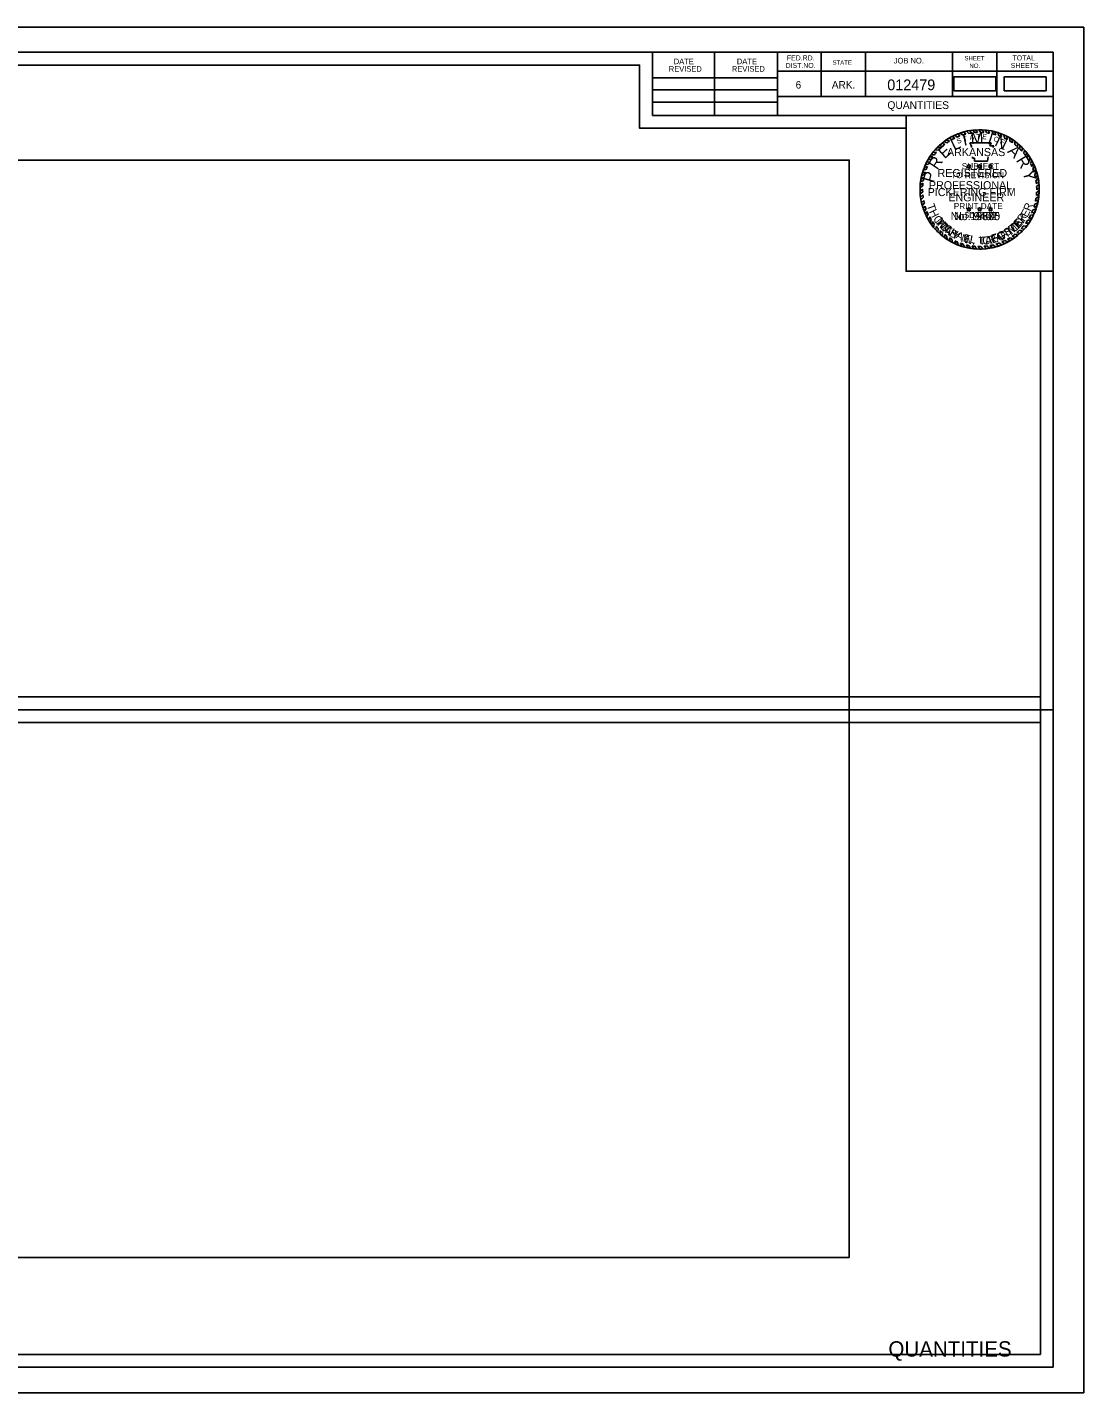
# Model space of a CAD drawing. Extents: x 1369290 to 1371547, y 379683 to 379897.
# Drawn here: x 1369823.5 to 1369988.6, y 379683.5 to 379896.8 of the extents above; entities that cross this region are included whole.
import ezdxf

# ---------------------------------------------------------------- set-up
doc = ezdxf.new("R2010")
doc.units = 0
for name, color, linetype in [('Default', 7, 'Continuous'), ('R_Border', 7, 'Continuous'), ('R_Border Notes', 7, 'Continuous'), ('R_Border Plan-Plan', 7, 'Continuous'), ('R_Border Title', 7, 'Continuous'), ('R_No Plot', 7, 'Continuous'), ('STAMP_PE_CRAFTON', 7, 'Continuous'), ('STAMP_PE_FOSTER', 7, 'Continuous'), ('STAMP_PE_SEAL-INFO', 7, 'Continuous'), ('STAMP_PE_TAEGTMEYER', 7, 'Continuous'), ('STAMP_PE_TXT', 7, 'Continuous'), ('STAMP_PRELIMINARY', 7, 'Continuous')]:
    doc.layers.add(name, color=color, linetype=linetype)

msp = doc.modelspace()

# ---------------------------------------------------------------- linework, layer by layer
at = {"layer": 'Default'}
for points in [[(1369968.28, 379886.89), (1369974.85, 379886.89), (1369974.85, 379889.08), (1369968.28, 379889.08)], [(1369976.15, 379886.89), (1369982.72, 379886.89), (1369982.72, 379889.08), (1369976.15, 379889.08)], [(1369691.88, 379704.61), (1369951.95, 379704.61), (1369951.95, 379876.08), (1369691.88, 379876.08)]]:
    msp.add_lwpolyline(points, close=True, dxfattribs=at)
at = {"layer": 'R_Border'}
for p, q in [((1369667.65, 379892.93), (1369983.83, 379892.93)), ((1369921.19, 379883.05), (1369921.19, 379892.93)), ((1369930.87, 379883.05), (1369930.87, 379892.93)), ((1369940.73, 379892.93), (1369940.73, 379883.05)), ((1369947.57, 379892.93), (1369947.57, 379885.99)), ((1369954.51, 379892.93), (1369954.51, 379885.99)), ((1369968.09, 379892.93), (1369968.09, 379885.99)), ((1369975.03, 379892.93), (1369975.03, 379885.99)), ((1369983.83, 379687.47), (1369983.83, 379892.93)), ((1369921.19, 379888.91), (1369940.73, 379888.91)), ((1369983.83, 379889.99), (1369940.73, 379889.99)), ((1369983.83, 379890.01), (1369983.83, 379890.01)), ((1369921.19, 379887.05), (1369940.73, 379887.05)), ((1369921.19, 379885.11), (1369940.73, 379885.11)), ((1369983.83, 379885.99), (1369940.73, 379885.99)), ((1369943.69, 379885.99), (1369983.83, 379885.99)), ((1369983.83, 379883.05), (1369921.19, 379883.05)), ((1369983.83, 379687.47), (1369667.65, 379687.47))]:
    msp.add_line(p, q, dxfattribs=at)
at = {"layer": 'R_Border Plan-Plan'}
msp.add_line((1369667.65, 379790.2), (1369983.83, 379790.2), dxfattribs=at)
at = {"layer": 'R_No Plot'}
for points in [[(1369655.25, 379896.82), (1369988.59, 379896.82), (1369988.59, 379683.48), (1369655.25, 379683.48)], [(1369981.83, 379792.2), (1369669.65, 379792.2), (1369669.65, 379890.93), (1369919.19, 379890.93), (1369919.19, 379881.05), (1369936.73, 379881.05), (1369960.83, 379881.05), (1369960.83, 379858.71), (1369981.83, 379858.71)], [(1369669.65, 379890.93), (1369919.19, 379890.93), (1369919.19, 379881.05), (1369936.73, 379881.05), (1369960.83, 379881.05), (1369960.83, 379858.71), (1369981.83, 379858.71), (1369981.83, 379689.47), (1369669.65, 379689.47)], [(1369960.83, 379883.05), (1369983.83, 379883.05), (1369983.83, 379858.71), (1369960.83, 379858.71)], [(1369669.65, 379788.2), (1369981.83, 379788.2), (1369981.83, 379689.47), (1369669.65, 379689.47)]]:
    msp.add_lwpolyline(points, close=True, dxfattribs=at)
at = {"layer": 'STAMP_PE_SEAL-INFO'}
for p, q in [((1369968.01, 379879.75), (1369968.47, 379879.52)), ((1369968.44, 379879.96), (1369968.83, 379879.68)), ((1369968.95, 379880.18), (1369969.24, 379879.85)), ((1369969.29, 379880.3), (1369969.67, 379880)), ((1369969.88, 379880.49), (1369970.17, 379880.14)), ((1369970.27, 379880.58), (1369970.63, 379880.24)), ((1369970.75, 379880.68), (1369971.05, 379880.31)), ((1369971.27, 379880.75), (1369971.55, 379880.37)), ((1369972.01, 379880.4), (1369971.69, 379880.79)), ((1369972.5, 379880.4), (1369972.22, 379880.81)), ((1369972.96, 379880.38), (1369972.7, 379880.81)), ((1369973.47, 379880.33), (1369973.18, 379880.77)), ((1369973.89, 379880.27), (1369973.64, 379880.72)), ((1369974.46, 379880.15), (1369974.28, 379880.61)), ((1369974.86, 379880.04), (1369974.7, 379880.51)), ((1369975.31, 379879.89), (1369975.17, 379880.37)), ((1369975.73, 379879.73), (1369975.58, 379880.23)), ((1369976.19, 379879.53), (1369976.09, 379880.02)), ((1369976.63, 379879.3), (1369976.55, 379879.81)), ((1369965.37, 379877.69), (1369965.89, 379877.65)), ((1369965.7, 379878.04), (1369966.24, 379877.99)), ((1369966.03, 379878.36), (1369966.49, 379878.22)), ((1369966.37, 379878.66), (1369966.9, 379878.56)), ((1369966.75, 379878.99), (1369967.21, 379878.78)), ((1369967.17, 379879.25), (1369967.61, 379879.05)), ((1369967.56, 379879.5), (1369967.99, 379879.27)), ((1369970.81, 379878.78), (1369974.15, 379878.78)), ((1369970.93, 379878.47), (1369970.81, 379878.78)), ((1369971.03, 379878.18), (1369970.93, 379878.47)), ((1369971.04, 379878.06), (1369971.03, 379878.18)), ((1369974.15, 379878.78), (1369973.93, 379878.29)), ((1369973.93, 379878.29), (1369974.56, 379878.29)), ((1369974.56, 379878.29), (1369974.41, 379878.06)), ((1369977.02, 379879.07), (1369976.98, 379879.57)), ((1369977.46, 379878.78), (1369977.42, 379879.3)), ((1369977.82, 379878.52), (1369977.85, 379879)), ((1369978.26, 379878.15), (1369978.28, 379878.67)), ((1369978.58, 379877.85), (1369978.65, 379878.35)), ((1369978.93, 379877.48), (1369979, 379878.01)), ((1369979.21, 379877.16), (1369979.35, 379877.63)), ((1369963.85, 379875.35), (1369964.35, 379875.46)), ((1369964.04, 379875.74), (1369964.54, 379875.81)), ((1369964.27, 379876.17), (1369964.76, 379876.19)), ((1369964.51, 379876.57), (1369965.03, 379876.6)), ((1369964.75, 379876.91), (1369965.25, 379876.91)), ((1369965.03, 379877.28), (1369965.58, 379877.3)), ((1369971.23, 379876.35), (1369971.2, 379876.57)), ((1369971.54, 379876.35), (1369971.23, 379876.35)), ((1369971.54, 379875.92), (1369971.54, 379876.35)), ((1369973.57, 379875.92), (1369971.54, 379875.92)), ((1369973.59, 379876.26), (1369973.57, 379875.92)), ((1369973.67, 379876.57), (1369973.59, 379876.26)), ((1369979.53, 379876.75), (1369979.67, 379877.25)), ((1369979.75, 379876.43), (1369979.93, 379876.89)), ((1369980.06, 379875.93), (1369980.24, 379876.42)), ((1369980.26, 379875.57), (1369980.49, 379876.01)), ((1369980.49, 379875.08), (1369980.72, 379875.57)), ((1369963.62, 379873.36), (1369963.15, 379873.11)), ((1369963.25, 379873.6), (1369963.72, 379873.8)), ((1369963.36, 379874.01), (1369963.84, 379874.18)), ((1369963.52, 379874.51), (1369964, 379874.65)), ((1369963.67, 379874.92), (1369964.17, 379875.07)), ((1369980.63, 379874.75), (1369980.9, 379875.18)), ((1369980.83, 379874.2), (1369981.1, 379874.67)), ((1369980.93, 379873.83), (1369981.23, 379874.28)), ((1369981.07, 379873.27), (1369981.39, 379873.72)), ((1369981.14, 379872.89), (1369981.49, 379873.25)), ((1369963.44, 379872.04), (1369963.02, 379871.78)), ((1369963.42, 379871.55), (1369963.02, 379871.21)), ((1369963.47, 379872.46), (1369963.04, 379872.18)), ((1369963.43, 379871.14), (1369963.04, 379870.81)), ((1369963.53, 379872.9), (1369963.09, 379872.68)), ((1369981.2, 379872.38), (1369981.57, 379872.72)), ((1369981.23, 379871.97), (1369981.62, 379872.26)), ((1369981.24, 379871.04), (1369981.66, 379871.32)), ((1369981.25, 379871.45), (1369981.65, 379871.77)), ((1369963.46, 379870.64), (1369963.09, 379870.29)), ((1369963.51, 379870.21), (1369963.16, 379869.84)), ((1369963.59, 379869.75), (1369963.25, 379869.39)), ((1369963.68, 379869.34), (1369963.37, 379868.92)), ((1369980.95, 379869.2), (1369981.42, 379869.4)), ((1369981.06, 379869.65), (1369981.51, 379869.84)), ((1369981.15, 379870.15), (1369981.59, 379870.37)), ((1369981.2, 379870.54), (1369981.63, 379870.79)), ((1369963.81, 379868.89), (1369963.51, 379868.47)), ((1369963.95, 379868.47), (1369963.67, 379868.05)), ((1369964.12, 379868.04), (1369963.85, 379867.62)), ((1369964.29, 379867.66), (1369964.06, 379867.19)), ((1369964.52, 379867.2), (1369964.33, 379866.71)), ((1369980.02, 379866.97), (1369980.52, 379867.03)), ((1369980.29, 379867.47), (1369980.78, 379867.54)), ((1369980.45, 379867.81), (1369980.94, 379867.9)), ((1369980.67, 379868.32), (1369981.15, 379868.45)), ((1369980.8, 379868.7), (1369981.29, 379868.9)), ((1369964.76, 379866.79), (1369964.57, 379866.32)), ((1369964.96, 379866.48), (1369964.85, 379865.93)), ((1369965.24, 379866.09), (1369965.14, 379865.56)), ((1369965.54, 379865.71), (1369965.46, 379865.19)), ((1369965.85, 379865.38), (1369965.79, 379864.85)), ((1369966.17, 379865.05), (1369966.14, 379864.52)), ((1369966.51, 379864.74), (1369966.51, 379864.21)), ((1369978.16, 379864.74), (1369978.63, 379864.61)), ((1369978.56, 379865.11), (1369979, 379864.97)), ((1369978.82, 379865.37), (1369979.29, 379865.29)), ((1369979.2, 379865.8), (1369979.66, 379865.73)), ((1369979.51, 379866.2), (1369980.01, 379866.2)), ((1369979.85, 379866.69), (1369980.32, 379866.69)), ((1369966.87, 379864.44), (1369966.89, 379863.92)), ((1369967.21, 379864.19), (1369967.25, 379863.68)), ((1369967.64, 379863.91), (1369967.7, 379863.4)), ((1369967.99, 379863.71), (1369968.08, 379863.19)), ((1369968.47, 379863.46), (1369968.63, 379862.94)), ((1369968.84, 379863.29), (1369969.02, 379862.78)), ((1369969.34, 379863.1), (1369969.55, 379862.59)), ((1369969.75, 379862.96), (1369969.97, 379862.47)), ((1369970.25, 379862.82), (1369970.47, 379862.36)), ((1369970.65, 379862.74), (1369970.9, 379862.28)), ((1369971.15, 379862.66), (1369971.39, 379862.21)), ((1369971.59, 379862.61), (1369971.86, 379862.18)), ((1369972.07, 379862.58), (1369972.38, 379862.17)), ((1369972.53, 379862.58), (1369972.88, 379862.18)), ((1369973.05, 379862.61), (1369973.38, 379862.23)), ((1369973.49, 379862.65), (1369973.86, 379862.29)), ((1369973.93, 379862.72), (1369974.32, 379862.38)), ((1369974.43, 379862.83), (1369974.8, 379862.5)), ((1369974.89, 379862.95), (1369975.3, 379862.65)), ((1369975.38, 379863.11), (1369975.82, 379862.84)), ((1369975.8, 379863.28), (1369976.22, 379863.02)), ((1369976.26, 379863.49), (1369976.74, 379863.28)), ((1369976.67, 379863.7), (1369977.08, 379863.47)), ((1369977.08, 379863.95), (1369977.53, 379863.75)), ((1369977.42, 379864.17), (1369977.86, 379863.98)), ((1369977.88, 379864.52), (1369978.35, 379864.37))]:
    msp.add_line(p, q, dxfattribs=at)
for radius, start, end in [(9.32, 117.6544, 120.8099), (9.32, 111.3124, 114.7026), (8.91, 110.3086, 113.1659), (9.32, 105.2339, 109.0352), (8.91, 104.0352, 107.3615), (9.32, 99.7525, 102.7765), (8.91, 98.258, 101.0329), (9.32, 93.9381, 96.5517), (8.91, 92.1102, 95.0367), (9.32, 87.7298, 90.6707), (8.91, 85.9628, 88.9097), (9.32, 81.9732, 84.8236), (8.91, 79.9264, 82.696), (9.32, 75.3125, 77.9426), (8.91, 73.5575, 76.2314), (9.32, 69.6061, 72.3058), (8.91, 67.6248, 70.504), (9.32, 63.1329, 66.2704), (9.32, 135.4021, 138.3031), (8.91, 133.1331, 136.2562), (9.32, 129.7326, 132.5376), (8.91, 127.5297, 130.9683), (9.32, 123.6199, 126.5906), (8.91, 121.9746, 125.11), (8.91, 115.6869, 119.1583), (8.91, 61.1558, 64.3784), (9.32, 56.9003, 60.0942), (8.91, 54.9238, 58.2702), (8.91, 48.3016, 52.0395), (9.32, 50.3492, 53.7159), (8.91, 42.2212, 45.5512), (9.32, 44.3405, 47.3929), (9.32, 38.1247, 41.2316), (9.32, 152.864, 155.5189), (9.32, 147.0072, 149.899), (8.91, 151.0315, 153.573), (9.32, 141.6056, 144.4486), (8.91, 145.0197, 148.2104), (8.91, 139.301, 142.5873), (8.91, 36.135, 39.5311), (8.91, 29.9032, 33.6645), (9.32, 31.9614, 35.4294), (8.91, 23.7732, 27.2211), (9.32, 25.9391, 29.0125), (9.32, 164.3068, 166.894), (9.32, 158.4077, 161.0701), (8.91, 167.9048, 170.9039), (8.91, 162.4331, 165.0013), (8.91, 156.3402, 159.2319), (8.91, 17.6802, 21.4251), (9.32, 19.9538, 23.3141), (8.91, 11.5444, 15.2364), (9.32, 13.8421, 17.4447), (9.32, 7.5852, 10.8621), (9.32, 175.7409, 178.2066), (9.32, 181.7251, 184.1626), (9.32, 170.0003, 172.6878), (8.91, 179.6454, 182.2633), (8.91, 173.73, 176.4734), (8.91, 5.7599, 9.0606), (8.91, 359.7329, 3.0639), (9.32, 1.7215, 4.7268), (9.32, 355.7156, 358.9569), (9.32, 187.4204, 190.1927), (9.32, 193.0369, 195.9973), (8.91, 185.4539, 188.234), (8.91, 191.2274, 193.9858), (8.91, 341.777, 345.0925), (8.91, 348.0778, 351.3435), (8.91, 353.8632, 357.1274), (9.32, 343.8925, 347.035), (9.32, 349.8305, 353.0885), (9.32, 198.8967, 201.6281), (8.91, 196.9675, 199.8353), (9.32, 204.5479, 207.4328), (8.91, 202.7761, 205.4791), (8.91, 208.7883, 211.7934), (8.91, 329.5549, 333.2076), (8.91, 335.6038, 339.1858), (9.32, 331.4037, 334.9332), (9.32, 337.3837, 340.9933), (9.32, 210.8636, 213.6571), (9.32, 216.6115, 219.491), (8.91, 214.1838, 217.2747), (9.32, 222.48, 225.3801), (8.91, 220.3909, 223.3056), (8.91, 226.2494, 229.2407), (8.91, 310.7744, 314.3161), (9.32, 312.4518, 315.6633), (8.91, 316.6531, 320.3711), (9.32, 318.2846, 321.8043), (8.91, 323.5851, 327.4407), (9.32, 325.4405, 328.9872), (9.32, 228.3665, 231.348), (8.91, 232.229, 234.9336), (9.32, 234.295, 236.9452), (8.91, 238.2223, 240.8353), (9.32, 240.1977, 242.8613), (8.91, 244.3204, 246.9486), (9.32, 246.576, 249.1558), (8.91, 250.3491, 253.1216), (9.32, 252.5967, 255.3252), (8.91, 256.505, 259.1192), (8.91, 262.3783, 265.2012), (8.91, 268.3215, 271.277), (8.91, 274.6157, 277.4486), (8.91, 280.3459, 283.5814), (8.91, 286.6423, 289.9783), (9.32, 288.5709, 291.9733), (8.91, 292.8745, 296.1185), (9.32, 294.6481, 298.2166), (8.91, 299.0768, 302.1724), (9.32, 300.621, 303.8703), (8.91, 304.823, 308.5143), (9.32, 306.3721, 310.208), (9.32, 258.4433, 261.1398), (9.32, 264.1978, 267.1009), (9.32, 270.2548, 273.3361), (9.32, 276.4239, 279.4357), (9.32, 282.3199, 285.3702)]:
    msp.add_arc((1369972.33, 379871.49), radius, start, end, dxfattribs=at)
at = {"layer": 'STAMP_PE_TXT'}
for p, q in [((1369970.56, 379875.21), (1369970.64, 379875.44)), ((1369970.64, 379875.44), (1369970.71, 379875.21)), ((1369972.26, 379875.21), (1369972.33, 379875.44)), ((1369972.33, 379875.44), (1369972.41, 379875.21)), ((1369973.96, 379875.21), (1369974.03, 379875.44)), ((1369974.03, 379875.44), (1369974.11, 379875.21)), ((1369970.51, 379875.06), (1369970.31, 379875.21)), ((1369970.31, 379875.21), (1369970.56, 379875.21)), ((1369970.44, 379874.83), (1369970.51, 379875.06)), ((1369970.64, 379874.97), (1369970.44, 379874.83)), ((1369970.83, 379874.83), (1369970.64, 379874.97)), ((1369970.71, 379875.21), (1369970.96, 379875.21)), ((1369970.96, 379875.21), (1369970.76, 379875.06)), ((1369970.76, 379875.06), (1369970.83, 379874.83)), ((1369972.21, 379875.06), (1369972.01, 379875.21)), ((1369972.01, 379875.21), (1369972.26, 379875.21)), ((1369972.14, 379874.83), (1369972.21, 379875.06)), ((1369972.33, 379874.97), (1369972.14, 379874.83)), ((1369972.53, 379874.83), (1369972.33, 379874.97)), ((1369972.41, 379875.21), (1369972.65, 379875.21)), ((1369972.65, 379875.21), (1369972.46, 379875.06)), ((1369972.46, 379875.06), (1369972.53, 379874.83)), ((1369973.91, 379875.06), (1369973.71, 379875.21)), ((1369973.71, 379875.21), (1369973.96, 379875.21)), ((1369973.83, 379874.83), (1369973.91, 379875.06)), ((1369974.03, 379874.97), (1369973.83, 379874.83)), ((1369974.23, 379874.83), (1369974.03, 379874.97)), ((1369974.11, 379875.21), (1369974.35, 379875.21)), ((1369974.35, 379875.21), (1369974.15, 379875.06)), ((1369974.15, 379875.06), (1369974.23, 379874.83)), ((1369970.51, 379868.35), (1369970.31, 379868.5)), ((1369970.31, 379868.5), (1369970.56, 379868.5)), ((1369970.44, 379868.12), (1369970.51, 379868.35)), ((1369970.64, 379868.27), (1369970.44, 379868.12)), ((1369970.56, 379868.5), (1369970.64, 379868.73)), ((1369970.64, 379868.73), (1369970.71, 379868.5)), ((1369970.83, 379868.12), (1369970.64, 379868.27)), ((1369970.71, 379868.5), (1369970.96, 379868.5)), ((1369970.96, 379868.5), (1369970.76, 379868.35)), ((1369970.76, 379868.35), (1369970.83, 379868.12)), ((1369972.21, 379868.35), (1369972.01, 379868.5)), ((1369972.01, 379868.5), (1369972.26, 379868.5)), ((1369972.14, 379868.12), (1369972.21, 379868.35)), ((1369972.33, 379868.27), (1369972.14, 379868.12)), ((1369972.26, 379868.5), (1369972.33, 379868.73)), ((1369972.33, 379868.73), (1369972.41, 379868.5)), ((1369972.53, 379868.12), (1369972.33, 379868.27)), ((1369972.41, 379868.5), (1369972.65, 379868.5)), ((1369972.65, 379868.5), (1369972.46, 379868.35)), ((1369972.46, 379868.35), (1369972.53, 379868.12)), ((1369973.91, 379868.35), (1369973.71, 379868.5)), ((1369973.71, 379868.5), (1369973.96, 379868.5)), ((1369973.83, 379868.12), (1369973.91, 379868.35)), ((1369974.03, 379868.27), (1369973.83, 379868.12)), ((1369973.96, 379868.5), (1369974.03, 379868.73)), ((1369974.03, 379868.73), (1369974.11, 379868.5)), ((1369974.23, 379868.12), (1369974.03, 379868.27)), ((1369974.11, 379868.5), (1369974.35, 379868.5)), ((1369974.35, 379868.5), (1369974.15, 379868.35)), ((1369974.15, 379868.35), (1369974.23, 379868.12))]:
    msp.add_line(p, q, dxfattribs=at)
at = {"layer": 'STAMP_PRELIMINARY'}
msp.add_circle((1369972.33, 379871.49), 9.32, dxfattribs=at)

# ---------------------------------------------------------------- texts
at = {"layer": 'R_Border'}
for s, height, p in [('FED.RD.', 0.782, (1369942.21, 379891.65)), ('TOTAL', 0.782, (1369977.47, 379891.65)), ('REVISED', 0.879, (1369923.75, 379889.88)), ('DATE', 0.879, (1369924.53, 379891.06)), ('REVISED', 0.879, (1369933.61, 379889.88)), ('DATE', 0.879, (1369934.39, 379891.06)), ('DIST.NO.', 0.782, (1369942.01, 379890.47)), ('STATE', 0.684, (1369949.33, 379890.97)), ('JOB NO.', 0.879, (1369958.91, 379891.17)), ('SHEET', 0.684, (1369969.95, 379891.65)), ('NO.', 0.684, (1369970.73, 379890.47)), ('SHEETS', 0.782, (1369977.19, 379890.47)), ('6', 1.17, (1369943.57, 379887.25)), ('ARK.', 1.172, (1369949.23, 379887.25))]:
    msp.add_text(s, height=height, dxfattribs=at).set_placement(p)
at = {"layer": 'R_Border Notes'}
for s, height, p in [('012479', 1.68, (1369957.89, 379886.99)), ('QUANTITIES', 1.2, (1369957.91, 379884.07))]:
    msp.add_text(s, height=height, dxfattribs=at).set_placement(p)
at = {"layer": 'R_Border Title'}
msp.add_text('QUANTITIES', height=2.4, dxfattribs=at).set_placement((1369958.07, 379689.12))
at = {"layer": 'STAMP_PE_CRAFTON'}
for s, rotation, p in [('T', 310.7442, (1369965.3, 379866.39)), ('N', 49.2411, (1369978.62, 379865.51)), ('O', 317.6422, (1369965.97, 379865.58)), ('N', 324.4537, (1369966.81, 379864.79)), ('Y', 331.1686, (1369967.85, 379864.08)), ('F', 28.7821, (1369975.99, 379863.62)), ('T', 34.1136, (1369976.91, 379864.13)), ('O', 41.8391, (1369977.77, 379864.73)), ('N', 347.4752, (1369969.9, 379863.16)), ('.', 356.8926, (1369971.13, 379862.88)), ('C', 6.0117, (1369972.81, 379862.83)), ('R', 14.8189, (1369973.9, 379862.95)), ('A', 20.5125, (1369975.01, 379863.25))]:
    msp.add_text(s, height=1.25, rotation=rotation, dxfattribs=at).set_placement(p)
msp.add_text('No. 12370', height=1.25, dxfattribs=at).set_placement((1369967.8, 379866.69))
at = {"layer": 'STAMP_PE_FOSTER'}
for s, rotation, p in [('M', 308.339, (1369965.45, 379866.51)), ('E', 46.9613, (1369978.33, 379865.48)), ('R', 54.5031, (1369979.06, 379866.3)), ('I', 314.1842, (1369966.25, 379865.57)), ('C', 319.8733, (1369966.6, 379865.22)), ('H', 327.7235, (1369967.53, 379864.48)), ('A', 335.7276, (1369968.51, 379863.9)), ('O', 23.719, (1369975.41, 379863.57)), ('S', 31.7234, (1369976.52, 379864.1)), ('T', 39.4194, (1369977.48, 379864.73)), ('E', 343.5779, (1369969.65, 379863.43)), ('L', 350.8115, (1369970.71, 379863.16)), ('L', 1.2666, (1369972.25, 379863)), ('.', 6.8035, (1369973.29, 379863.06)), ('F', 15.8691, (1369974.37, 379863.24))]:
    msp.add_text(s, height=1.2, rotation=rotation, dxfattribs=at).set_placement(p)
msp.add_text('No. 9402', height=1.25, dxfattribs=at).set_placement((1369968.32, 379866.69))
at = {"layer": 'STAMP_PE_TAEGTMEYER'}
for s, rotation, p in [('T', 289.646, (1369964.03, 379869)), ('R', 69.57, (1369980.28, 379868)), ('H', 296.7339, (1369964.39, 379868.02)), ('O', 303.7708, (1369964.98, 379866.91)), ('E', 46.8094, (1369978.37, 379865.27)), ('Y', 53.9986, (1369979.11, 379866.08)), ('E', 63.0984, (1369979.78, 379867.02)), ('M', 314.2033, (1369965.64, 379865.96)), ('A', 321.0594, (1369966.6, 379864.99)), ('S', 327.8239, (1369967.42, 379864.35)), ('G', 23.3052, (1369975.33, 379863.35)), ('T', 31.466, (1369976.43, 379863.84)), ('M', 39.3, (1369977.33, 379864.39)), ('N', 344.2727, (1369969.32, 379863.34)), ('.', 350.6464, (1369970.53, 379863.01)), ('T', 3.0061, (1369972.2, 379862.81)), ('A', 8.9826, (1369973.24, 379862.87)), ('E', 17.6836, (1369974.28, 379863.02))]:
    msp.add_text(s, height=1.25, rotation=rotation, dxfattribs=at).set_placement(p)
msp.add_text('No. 19605', height=1.25, dxfattribs=at).set_placement((1369967.8, 379866.69))
at = {"layer": 'STAMP_PE_TXT'}
for s, rotation, p in [('T', 16.311, (1369969.86, 379878.97)), ('A', 9.0679, (1369970.82, 379879.22)), ('T', 1.8248, (1369971.8, 379879.35)), ('E', 355.2002, (1369972.71, 379879.36)), ('O', 342.2506, (1369974.44, 379879.08)), ('S', 23.5541, (1369968.93, 379878.59)), ('F', 335.0075, (1369975.41, 379878.74))]:
    msp.add_text(s, height=0.781, rotation=rotation, dxfattribs=at).set_placement(p)
for s, p in [('ARKANSAS', (1369967.23, 379876.7)), ('REGISTERED', (1369965.75, 379873.43)), ('PROFESSIONAL', (1369964.4, 379871.53)), ('ENGINEER', (1369967.44, 379869.63))]:
    msp.add_text(s, height=1.25, dxfattribs=at).set_placement(p)
at = {"layer": 'STAMP_PRELIMINARY'}
for s, rotation, p in [('I', 12.5248, (1369969.87, 379878.28)), ('M', 3.1074, (1369970.97, 379878.59)), ('I', 342.3164, (1369973.44, 379878.65)), ('N', 333.9382, (1369974.54, 379878.38)), ('E', 42.3578, (1369966.86, 379876.19)), ('L', 25.513, (1369968.34, 379877.52)), ('A', 315.6579, (1369976.58, 379877.35)), ('R', 56.2292, (1369965.7, 379874.45)), ('R', 301.3831, (1369977.95, 379876.04)), ('P', 73.913, (1369965.16, 379872.43)), ('Y', 283.2593, (1369979.04, 379874.25))]:
    msp.add_text(s, height=1.8, rotation=rotation, dxfattribs=at).set_placement(p)
for s, height, p in [('SUBJECT', 0.96, (1369969.53, 379874.64)), ('TO REVISION', 0.96, (1369967.87, 379873.25)), ('PICKERING FIRM', 1.25, (1369964.21, 379870.45)), ('PRINT DATE', 0.96, (1369968.29, 379868.41)), ('$DATE$', 0.96, (1369969.97, 379867.02))]:
    msp.add_text(s, height=height, dxfattribs=at).set_placement(p)

doc.saveas('drawing.dxf')
